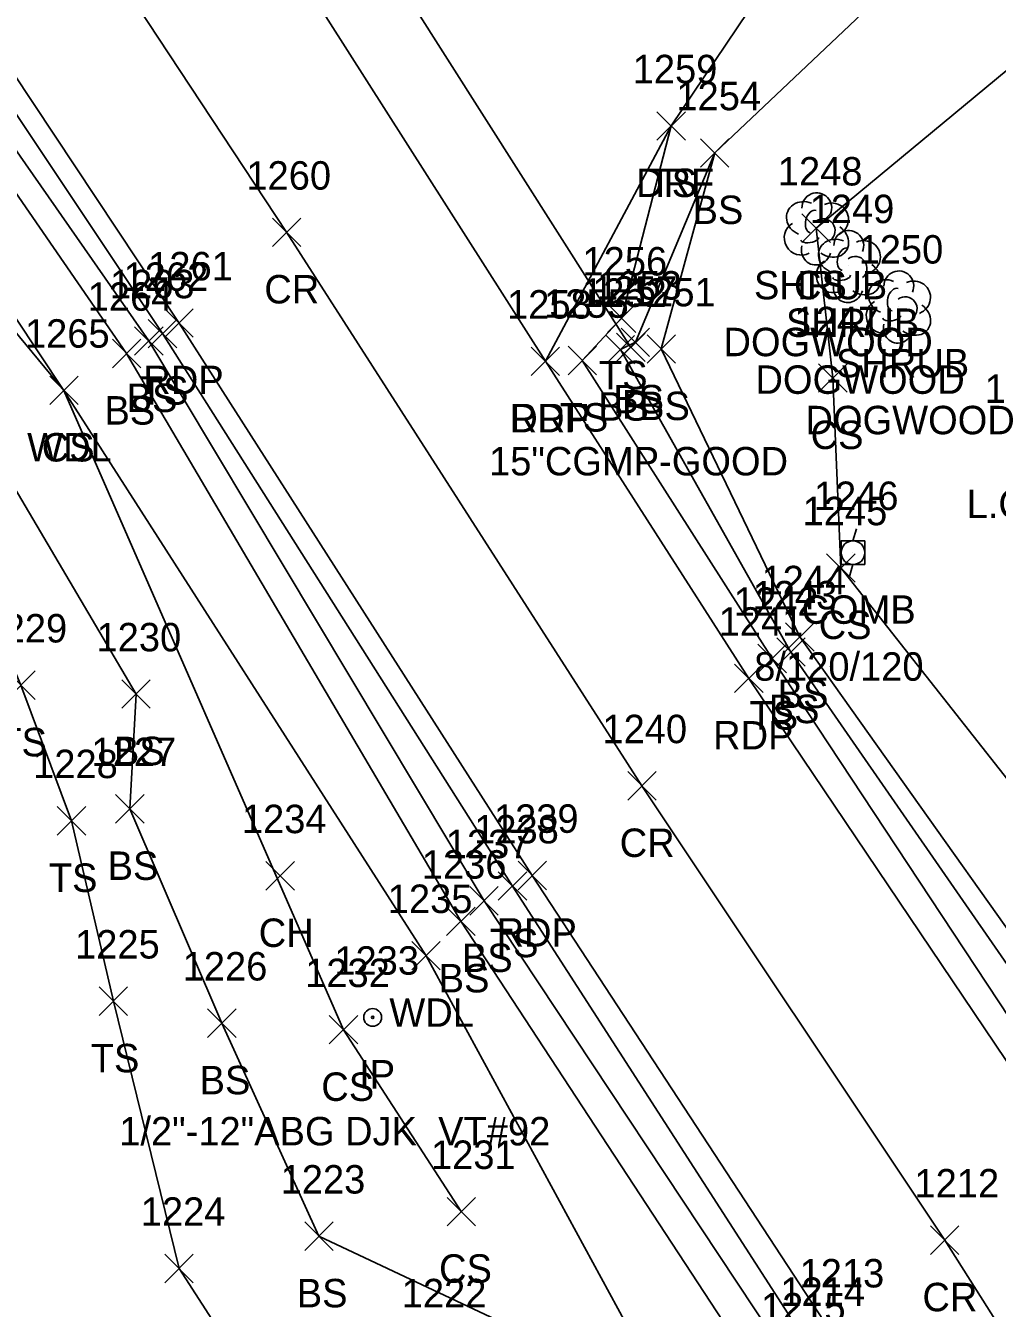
# Model space of a CAD drawing. Extents: x 1501299 to 1502485, y 381423 to 383765.
# Drawn here: x 1501751.5 to 1501819.8, y 382999.5 to 383089.7 of the extents above; entities that cross this region are included whole.
import ezdxf

# ---------------------------------------------------------------- set-up
doc = ezdxf.new("R2010")
doc.units = 0
for name, color, linetype in [('D_A', 7, 'Continuous'), ('D_C', 7, 'Continuous'), ('D_I', 7, 'Continuous'), ('D_TIC', 7, 'Continuous'), ('DCP', 7, 'Continuous'), ('L_A', 7, 'Continuous'), ('L_C', 7, 'Continuous'), ('L_I', 7, 'Continuous'), ('L_TIC', 7, 'Continuous'), ('LAWA', 7, 'Continuous'), ('LELB', 7, 'Continuous'), ('LSH', 7, 'Continuous'), ('M_A', 7, 'Continuous'), ('M_C', 7, 'Continuous'), ('M_I', 7, 'Continuous'), ('MPIR', 7, 'Continuous'), ('P_A', 7, 'Continuous'), ('P_I', 7, 'Continuous'), ('P_TIC', 7, 'Continuous'), ('PET', 7, 'Continuous'), ('PRC', 7, 'Continuous'), ('R_A', 7, 'Continuous'), ('R_I', 7, 'Continuous'), ('R_TIC', 7, 'Continuous'), ('RDF', 7, 'Continuous'), ('U_A', 7, 'Continuous'), ('U_C', 7, 'Continuous'), ('U_I', 7, 'Continuous'), ('UP', 7, 'Continuous')]:
    doc.layers.add(name, color=color, linetype=linetype)

msp = doc.modelspace()

# ---------------------------------------------------------------- linework, layer by layer
at = {"layer": 'D_TIC'}
for points in [[(1501792.995, 383066.07), (1501794.995, 383068.07)], [(1501794.995, 383066.07), (1501792.995, 383068.07)]]:
    msp.add_lwpolyline(points, dxfattribs=at)
at = {"layer": 'DCP'}
msp.add_lwpolyline([(1501793.995, 383067.07), (1501773.389, 383099.506)], dxfattribs=at)
at = {"layer": 'L_TIC'}
for points in [[(1501795.83, 383081.637), (1501797.83, 383083.637)], [(1501797.83, 383081.637), (1501795.83, 383083.637)], [(1501798.894, 383079.741), (1501800.894, 383081.741)], [(1501800.894, 383079.741), (1501798.894, 383081.741)], [(1501798.894, 383079.741), (1501800.894, 383081.741)], [(1501800.894, 383079.741), (1501798.894, 383081.741)], [(1501806.021, 383074.451), (1501808.021, 383076.451)], [(1501808.021, 383074.451), (1501806.021, 383076.451)], [(1501792.35, 383068.124), (1501794.35, 383070.124)], [(1501794.35, 383068.124), (1501792.35, 383070.124)], [(1501760.094, 383067.04), (1501762.094, 383069.04)], [(1501762.094, 383067.04), (1501760.094, 383069.04)], [(1501759.133, 383066.523), (1501761.133, 383068.523)], [(1501761.133, 383066.523), (1501759.133, 383068.523)], [(1501792.264, 383065.917), (1501794.264, 383067.917)], [(1501794.264, 383065.917), (1501792.264, 383067.917)], [(1501793.32, 383066.431), (1501795.32, 383068.431)], [(1501795.32, 383066.431), (1501793.32, 383068.431)], [(1501795.137, 383065.958), (1501797.137, 383067.958)], [(1501797.137, 383065.958), (1501795.137, 383067.958)], [(1501757.572, 383065.643), (1501759.572, 383067.643)], [(1501759.572, 383065.643), (1501757.572, 383067.643)], [(1501789.589, 383065.151), (1501791.589, 383067.151)], [(1501791.589, 383065.151), (1501789.589, 383067.151)], [(1501807.19, 383063.923), (1501809.19, 383065.923)], [(1501809.19, 383063.923), (1501807.19, 383065.923)], [(1501753.165, 383063.049), (1501755.165, 383065.049)], [(1501755.165, 383063.049), (1501753.165, 383065.049)], [(1501753.165, 383063.049), (1501755.165, 383065.049)], [(1501755.165, 383063.049), (1501753.165, 383065.049)], [(1501807.759, 383050.568), (1501809.759, 383052.568)], [(1501809.759, 383050.568), (1501807.759, 383052.568)], [(1501804.875, 383045.715), (1501806.875, 383047.715)], [(1501806.875, 383045.715), (1501804.875, 383047.715)], [(1501802.928, 383044.204), (1501804.928, 383046.204)], [(1501804.928, 383044.204), (1501802.928, 383046.204)], [(1501804.246, 383044.654), (1501806.246, 383046.654)], [(1501806.246, 383044.654), (1501804.246, 383046.654)], [(1501750.145, 383042.326), (1501752.145, 383044.326)], [(1501752.145, 383042.326), (1501750.145, 383044.326)], [(1501758.234, 383041.702), (1501760.234, 383043.702)], [(1501760.234, 383041.702), (1501758.234, 383043.702)], [(1501757.794, 383033.635), (1501759.794, 383035.635)], [(1501759.794, 383033.635), (1501757.794, 383035.635)], [(1501753.694, 383032.791), (1501755.694, 383034.791)], [(1501755.694, 383032.791), (1501753.694, 383034.791)], [(1501768.363, 383028.922), (1501770.363, 383030.922)], [(1501770.363, 383028.922), (1501768.363, 383030.922)], [(1501784.685, 383028.202), (1501786.685, 383030.202)], [(1501786.685, 383028.202), (1501784.685, 383030.202)], [(1501782.687, 383027.162), (1501784.687, 383029.162)], [(1501784.687, 383027.162), (1501782.687, 383029.162)], [(1501781.057, 383025.726), (1501783.057, 383027.726)], [(1501783.057, 383025.726), (1501781.057, 383027.726)], [(1501778.613, 383023.31), (1501780.613, 383025.31)], [(1501780.613, 383023.31), (1501778.613, 383025.31)], [(1501756.64, 383020.11), (1501758.64, 383022.11)], [(1501758.64, 383020.11), (1501756.64, 383022.11)], [(1501764.256, 383018.564), (1501766.256, 383020.564)], [(1501766.256, 383018.564), (1501764.256, 383020.564)], [(1501764.256, 383018.564), (1501766.256, 383020.564)], [(1501766.256, 383018.564), (1501764.256, 383020.564)], [(1501772.809, 383018.102), (1501774.809, 383020.102)], [(1501774.809, 383018.102), (1501772.809, 383020.102)], [(1501781.082, 383005.317), (1501783.082, 383007.317)], [(1501783.082, 383005.317), (1501781.082, 383007.317)], [(1501771.083, 383003.589), (1501773.083, 383005.589)], [(1501773.083, 383003.589), (1501771.083, 383005.589)], [(1501761.256, 383001.321), (1501763.256, 383003.321)], [(1501763.256, 383001.321), (1501761.256, 383003.321)]]:
    msp.add_lwpolyline(points, dxfattribs=at)
at = {"layer": 'LAWA'}
msp.add_lwpolyline([(1501942.677, 382714.841), (1501935.183, 382744.721), (1501913.337, 382785.2), (1501893.395, 382826.433), (1501865.291, 382869.925), (1501854.75, 382888.13), (1501835.928, 382927.55), (1501822.234, 382953.468), (1501796.607, 382993.044), (1501779.613, 383024.31), (1501754.165, 383064.049), (1501733.525, 383095.142)], dxfattribs=at)
at = {"layer": 'LELB'}
for points in [[(1501947.071, 382716.202), (1501936.789, 382745.616), (1501921.74, 382787.499), (1501900.168, 382829.778), (1501877.018, 382875.801), (1501866.166, 382892.912), (1501844.624, 382932.733), (1501828.058, 382959.038), (1501805.265, 382995.601), (1501783.687, 383028.162), (1501760.133, 383067.523), (1501734.806, 383103.876), (1501716.067, 383128.727), (1501702.976, 383136.285), (1501694.191, 383132.723)], [(1501947.958, 382716.119), (1501939.996, 382745.704), (1501923.414, 382788.324), (1501902.81, 382830.435), (1501868.959, 382893.881), (1501846.402, 382933.734), (1501830.033, 382960.147), (1501806.634, 382996.692), (1501785.685, 383029.202), (1501761.094, 383068.04), (1501736.237, 383105.316), (1501718.865, 383131.579)], [(1501945.344, 382716.136), (1501936.673, 382745.194), (1501918.388, 382786.659), (1501897.882, 382827.989), (1501871.615, 382874.073), (1501860.416, 382890.256), (1501841.87, 382931.652), (1501826.472, 382956.951), (1501803.66, 382993.76), (1501782.057, 383026.726), (1501758.572, 383066.643), (1501733.616, 383102.86), (1501712.412, 383124.491), (1501694.918, 383122.167), (1501687.272, 383121.659)], [(1501869.881, 382950.686), (1501868.769, 382950.2), (1501850.126, 382976.258), (1501827.93, 383012.856), (1501805.246, 383045.654), (1501793.264, 383066.917), (1501794.32, 383067.431), (1501799.894, 383080.741), (1501815.831, 383095.832), (1501838.892, 383122.309)], [(1501783.593, 382899.612), (1501783.944, 382929.093), (1501780.21, 382962.679), (1501777.228, 382979.105), (1501762.256, 383002.321), (1501757.64, 383021.11), (1501754.694, 383033.791), (1501751.145, 383043.326), (1501742.41, 383064.134), (1501735.879, 383077.84), (1501726.8, 383086.928), (1501711.19, 383095.349), (1501693.409, 383100.221), (1501689.588, 383108.897)], [(1501782.082, 383006.317), (1501773.809, 383019.102), (1501754.165, 383064.049), (1501731.35, 383091.675), (1501722.185, 383098.36), (1501712.766, 383102.523), (1501700.661, 383104.877), (1501689.588, 383108.897)], [(1501872.664, 382953.638), (1501855.947, 382979.919), (1501835.173, 383018.012), (1501808.759, 383051.568), (1501808.19, 383064.923), (1501807.021, 383075.451), (1501821.181, 383087.198), (1501841.551, 383105.554)], [(1501860.53, 382958.003), (1501849.203, 382975.471), (1501826.17, 383011.487), (1501803.928, 383045.204), (1501790.589, 383066.151), (1501793.35, 383069.124), (1501796.83, 383082.637)], [(1501869.881, 382950.686), (1501852.369, 382977.849), (1501829.357, 383013.645), (1501805.875, 383046.715), (1501796.137, 383066.958), (1501799.894, 383080.741)], [(1501765.256, 383019.564), (1501758.794, 383034.635), (1501759.234, 383042.702), (1501748.322, 383061.182), (1501735.879, 383077.84)], [(1501796.607, 382993.044), (1501772.083, 383004.589), (1501765.256, 383019.564)]]:
    msp.add_lwpolyline(points, dxfattribs=at)
at = {"layer": 'LSH'}
for p, q in [((1501807.021, 383075.451), (1501807.021, 383075.451)), ((1501807.021, 383075.451), (1501807.021, 383075.451)), ((1501809.266, 383072.805), (1501809.266, 383072.805)), ((1501809.266, 383072.805), (1501809.266, 383072.805)), ((1501812.782, 383069.962), (1501812.782, 383069.962)), ((1501812.782, 383069.962), (1501812.782, 383069.962))]:
    msp.add_line(p, q, dxfattribs=at)
for centre in [(1501807.068, 383076.885), (1501809.313, 383074.239), (1501812.829, 383071.396)]:
    msp.add_arc(centre, 1.047, 335.52715, 180.95627, dxfattribs=at)
for centre, major_axis, ratio, start_param, end_param in [((1501806.229, 383076.117), (1.21, -0.512), 0.895232, 1.570796, 4.712389), ((1501806.812, 383075.909), (-0.208, -0.792), 0.645439, 3.141593, 6.283185), ((1501808.062, 383076.034), (-1.141, -0.483), 0.949671, 1.570796, 4.712389), ((1501807.521, 383075.284), (-0.5, 0.667), 0.989748, 3.141593, 6.283185), ((1501805.938, 383074.742), (0.584, -1.042), 0.959034, 3.141593, 6.283185), ((1501808.021, 383074.618), (-1.09, 0.792), 0.841452, 1.570796, 4.712389), ((1501807.021, 383073.951), (0.265, 1.061), 0.942809, 1.570796, 4.712389), ((1501806.563, 383074.701), (-0.625, -0.083), 0.423636, 0, 3.141593), ((1501808.474, 383073.471), (1.21, -0.512), 0.895232, 1.570796, 4.712389), ((1501809.057, 383073.263), (-0.208, -0.792), 0.645439, 3.141593, 6.283185), ((1501810.307, 383073.388), (-1.141, -0.483), 0.949671, 1.570796, 4.712389), ((1501808.183, 383072.096), (0.584, -1.042), 0.959034, 3.141593, 6.283185), ((1501809.766, 383072.638), (-0.5, 0.667), 0.989748, 3.141593, 6.283185), ((1501810.266, 383071.971), (-1.09, 0.792), 0.841452, 1.570796, 4.712389), ((1501809.266, 383071.305), (0.265, 1.061), 0.942809, 1.570796, 4.712389), ((1501808.808, 383072.054), (-0.625, -0.083), 0.423636, 0, 3.141593), ((1501811.99, 383070.628), (1.21, -0.512), 0.895232, 1.570796, 4.712389), ((1501813.824, 383070.545), (-1.141, -0.483), 0.949671, 1.570796, 4.712389), ((1501812.574, 383070.42), (-0.208, -0.792), 0.645439, 3.141593, 6.283185), ((1501813.282, 383069.795), (-0.5, 0.667), 0.989748, 3.141593, 6.283185), ((1501811.699, 383069.253), (0.584, -1.042), 0.959034, 3.141593, 6.283185), ((1501813.782, 383069.129), (-1.09, 0.792), 0.841452, 1.570796, 4.712389), ((1501812.782, 383068.462), (0.265, 1.061), 0.942809, 1.570796, 4.712389), ((1501812.324, 383069.212), (-0.625, -0.083), 0.423636, 0, 3.141593)]:
    msp.add_ellipse(centre, major_axis=major_axis, ratio=ratio, start_param=start_param, end_param=end_param, dxfattribs=at)
at = {"layer": 'MPIR'}
for radius in [0.625, 0.0833]:
    msp.add_circle((1501775.859, 383019.972), radius, dxfattribs=at)
at = {"layer": 'P_TIC'}
for points in [[(1501768.812, 383074.158), (1501770.812, 383076.158)], [(1501770.812, 383074.158), (1501768.812, 383076.158)], [(1501761.257, 383067.782), (1501763.257, 383069.782)], [(1501763.257, 383067.782), (1501761.257, 383069.782)], [(1501786.994, 383065.094), (1501788.994, 383067.094)], [(1501788.994, 383065.094), (1501786.994, 383067.094)], [(1501801.294, 383042.804), (1501803.294, 383044.804)], [(1501803.294, 383042.804), (1501801.294, 383044.804)], [(1501793.783, 383035.247), (1501795.783, 383037.247)], [(1501795.783, 383035.247), (1501793.783, 383037.247)], [(1501786.075, 383028.946), (1501788.075, 383030.946)], [(1501788.075, 383028.946), (1501786.075, 383030.946)], [(1501815.055, 383003.313), (1501817.055, 383005.313)], [(1501817.055, 383003.313), (1501815.055, 383005.313)]]:
    msp.add_lwpolyline(points, dxfattribs=at)
at = {"layer": 'PET'}
for points in [[(1501949.648, 382716.507), (1501941.04, 382745.977), (1501925.012, 382788.592), (1501904.253, 382831.621), (1501880.763, 382877.887), (1501870.565, 382894.723), (1501847.406, 382934.273), (1501830.938, 382961.01), (1501807.981, 382997.987), (1501787.075, 383029.946), (1501762.257, 383068.782), (1501737.378, 383106.292), (1501722.895, 383129.668), (1501696.699, 383166.339)], [(1501971.372, 382720.654), (1501961.032, 382754.708), (1501942.926, 382798.84), (1501930.998, 382825.078), (1501924.576, 382839.599), (1501916.528, 382851.603), (1501908.311, 382868.386), (1501899.175, 382885.527), (1501887.899, 382904.195), (1501878.505, 382922.493), (1501869.738, 382936.529), (1501858.065, 382956.489), (1501847.469, 382974.349), (1501824.868, 383010.254), (1501802.294, 383043.804), (1501787.994, 383066.094), (1501768.484, 383096.751)]]:
    msp.add_lwpolyline(points, dxfattribs=at)
at = {"layer": 'PRC'}
msp.add_lwpolyline([(1501960.612, 382718.648), (1501950.96, 382750.482), (1501934.965, 382791.852), (1501913.074, 382836.935), (1501889.309, 382881.383), (1501879.244, 382899.507), (1501856.391, 382940.32), (1501839.674, 382966.998), (1501816.055, 383004.313), (1501794.783, 383036.247), (1501769.812, 383075.158), (1501745.791, 383111.558), (1501729.435, 383136.001), (1501711.236, 383163.535), (1501694.816, 383188.199), (1501683.547, 383204.004), (1501664.644, 383231.239), (1501639.517, 383268.342), (1501626.393, 383287.881)], dxfattribs=at)
at = {"layer": 'R_TIC'}
for points in [[(1501795.83, 383081.637), (1501797.83, 383083.637)], [(1501797.83, 383081.637), (1501795.83, 383083.637)], [(1501786.994, 383065.094), (1501788.994, 383067.094)], [(1501788.994, 383065.094), (1501786.994, 383067.094)]]:
    msp.add_lwpolyline(points, dxfattribs=at)
at = {"layer": 'RDF'}
msp.add_lwpolyline([(1501787.994, 383066.094), (1501796.83, 383082.637), (1501809.2, 383101.04), (1501832.482, 383134.198)], dxfattribs=at)
at = {"layer": 'UP'}
for p, q in [((1501809.856, 383054.306), (1501809.606, 383053.473)), ((1501808.773, 383051.806), (1501808.773, 383053.473)), ((1501808.773, 383053.473), (1501810.44, 383053.473)), ((1501810.44, 383053.473), (1501810.44, 383051.806)), ((1501809.606, 383052.639), (1501809.606, 383052.639)), ((1501810.44, 383051.806), (1501808.773, 383051.806)), ((1501809.356, 383050.973), (1501809.606, 383051.806))]:
    msp.add_line(p, q, dxfattribs=at)
msp.add_circle((1501809.606, 383052.639), 0.833, dxfattribs=at)

# ---------------------------------------------------------------- texts
at = {"layer": 'D_A'}
msp.add_text('P', height=2, dxfattribs=at).set_placement((1501793.373, 383062.07))
at = {"layer": 'D_C'}
msp.add_text('15"CGMP-GOOD', height=2, dxfattribs=at).set_placement((1501784.035, 383058.07))
at = {"layer": 'D_I'}
msp.add_text('1257', height=2, dxfattribs=at).set_placement((1501791.303, 383070.07))
at = {"layer": 'L_A'}
for s, p in [('TS', (1501795.24, 383077.637)), ('BS', (1501798.335, 383075.741)), ('BS', (1501798.335, 383075.741)), ('SHRUB', (1501802.651, 383070.451)), ('CS', (1501805.462, 383070.451)), ('SHRUB', (1501804.896, 383067.805)), ('SHRUB', (1501808.412, 383064.962)), ('TS', (1501791.76, 383064.124)), ('TS', (1501759.503, 383063.04)), ('BS', (1501758.574, 383062.523)), ('BS', (1501792.761, 383062.431)), ('BS', (1501757.013, 383061.643)), ('BS', (1501791.704, 383061.917)), ('BS', (1501794.578, 383061.958)), ('TS', (1501788.998, 383061.151)), ('CS', (1501806.631, 383059.923)), ('WDL', (1501751.582, 383059.049)), ('CS', (1501752.606, 383059.049)), ('CS', (1501807.2, 383046.568)), ('BS', (1501804.316, 383041.715)), ('BS', (1501803.687, 383040.654)), ('TS', (1501802.338, 383040.204)), ('TS', (1501749.554, 383038.326)), ('BS', (1501757.675, 383037.702)), ('BS', (1501757.235, 383029.635)), ('TS', (1501753.103, 383028.791)), ('CH', (1501767.851, 383024.922)), ('TS', (1501784.094, 383024.202)), ('BS', (1501782.128, 383023.162)), ('BS', (1501780.498, 383021.726)), ('WDL', (1501777.03, 383019.31)), ('TS', (1501756.049, 383016.11)), ('BS', (1501763.697, 383014.564)), ('BS', (1501763.697, 383014.564)), ('CS', (1501772.25, 383014.102)), ('CS', (1501780.523, 383001.317)), ('BS', (1501770.524, 382999.589))]:
    msp.add_text(s, height=2, dxfattribs=at).set_placement(p)
at = {"layer": 'L_C'}
for s, p in [('DOGWOOD', (1501800.509, 383066.451)), ('DOGWOOD', (1501802.754, 383063.805)), ('DOGWOOD', (1501806.27, 383060.962)), ('L.CEDAR', (1501817.594, 383055.076))]:
    msp.add_text(s, height=2, dxfattribs=at).set_placement(p)
at = {"layer": 'L_I'}
for s, p in [('1259', (1501794.13, 383085.637)), ('1254', (1501797.201, 383083.741)), ('1254', (1501797.201, 383083.741)), ('1248', (1501804.328, 383078.451)), ('1248', (1501804.328, 383078.451)), ('1249', (1501806.565, 383075.805)), ('1250', (1501810.003, 383072.962)), ('1256', (1501790.602, 383072.124)), ('1263', (1501757.393, 383070.523)), ('1262', (1501758.354, 383071.04)), ('1253', (1501791.627, 383070.431)), ('1264', (1501755.833, 383069.643)), ('1252', (1501790.571, 383069.917)), ('1251', (1501794.011, 383069.958)), ('1255', (1501787.896, 383069.151)), ('1247', (1501805.497, 383067.923)), ('1265', (1501751.425, 383067.049)), ('1265', (1501751.425, 383067.049)), ('1200', (1501818.87, 383063.169)), ('1245', (1501806.067, 383054.568)), ('1244', (1501803.182, 383049.715)), ('1243', (1501802.553, 383048.654)), ('1242', (1501801.236, 383048.204)), ('1229', (1501748.444, 383046.326)), ('1230', (1501756.455, 383045.702)), ('1227', (1501756.101, 383037.635)), ('1228', (1501752.001, 383036.791)), ('1234', (1501766.67, 383032.922)), ('1238', (1501782.992, 383032.202)), ('1237', (1501780.994, 383031.162)), ('1236', (1501779.31, 383029.726)), ('1235', (1501776.92, 383027.31)), ('1225', (1501754.947, 383024.11)), ('1226', (1501762.508, 383022.564)), ('1226', (1501762.508, 383022.564)), ('1232', (1501771.116, 383022.102)), ('1231', (1501779.956, 383009.317)), ('1223', (1501769.39, 383007.589)), ('1224', (1501759.564, 383005.321)), ('1222', (1501777.902, 382999.592)), ('1214', (1501804.508, 382999.692)), ('1215', (1501803.139, 382998.601))]:
    msp.add_text(s, height=2, dxfattribs=at).set_placement(p)
at = {"layer": 'M_A'}
msp.add_text('IP', height=2, dxfattribs=at).set_placement((1501774.906, 383014.972))
at = {"layer": 'M_C'}
msp.add_text('1/2"-12"ABG DJK  VT#92', height=2, dxfattribs=at).set_placement((1501758.049, 383010.972))
at = {"layer": 'M_I'}
msp.add_text('1233', height=2, dxfattribs=at).set_placement((1501773.166, 383022.972))
at = {"layer": 'P_A'}
for s, p in [('CR', (1501768.245, 383070.158)), ('RDP', (1501759.746, 383063.782)), ('RDP', (1501785.482, 383061.094)), ('RDP', (1501799.782, 383038.804)), ('CR', (1501793.216, 383031.247)), ('RDP', (1501784.563, 383024.946)), ('CR', (1501814.488, 382999.313))]:
    msp.add_text(s, height=2, dxfattribs=at).set_placement(p)
at = {"layer": 'P_I'}
for s, p in [('1260', (1501766.986, 383078.158)), ('1261', (1501760.084, 383071.782)), ('1258', (1501785.301, 383069.094)), ('1241', (1501800.168, 383046.804)), ('1240', (1501792.003, 383039.247)), ('1239', (1501784.375, 383032.946)), ('1212', (1501813.93, 383007.313)), ('1213', (1501805.855, 383000.987))]:
    msp.add_text(s, height=2, dxfattribs=at).set_placement(p)
at = {"layer": 'R_A'}
for p in [(1501794.366, 383077.637), (1501785.529, 383061.094)]:
    msp.add_text('DRF', height=2, dxfattribs=at).set_placement(p)
at = {"layer": 'R_I'}
for s, p in [('1259', (1501794.13, 383085.637)), ('1258', (1501785.301, 383069.094))]:
    msp.add_text(s, height=2, dxfattribs=at).set_placement(p)
at = {"layer": 'U_A'}
msp.add_text('COMB', height=2, dxfattribs=at).set_placement((1501805.992, 383047.639))
at = {"layer": 'U_C'}
msp.add_text('8/120/120', height=2, dxfattribs=at).set_placement((1501802.67, 383043.639))
at = {"layer": 'U_I'}
msp.add_text('1246', height=2, dxfattribs=at).set_placement((1501806.859, 383055.639))

doc.saveas('drawing.dxf')
